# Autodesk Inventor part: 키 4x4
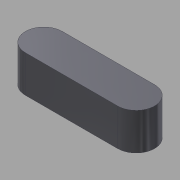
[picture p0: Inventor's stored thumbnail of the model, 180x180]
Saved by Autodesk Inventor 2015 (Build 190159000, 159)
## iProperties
Created: 2014-10
Part Number: 키 4x4
Document SubType Name: Modeling
Designer: KYOUNG IL JANG
Density: 7.86 g/cm^3
Mass: 1.65269 g
Surface Area: 2.35398 cm^2
Volume: 0.210265 cm^3
Material: 강철, 연강
Appearance: 강철 - 광택
Author: SeoGD™ [www.esajin.kr]
Revision Number: 1
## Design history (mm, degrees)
sketch "스케치1"
  geometry: L1 (-5, -2)-(5, -2); L2 (5, 2)-(-5, 2); A1 r 2 centre (5, 0) between (5, -2) and (5, 2); A2 r 2 centre (-5, 0) between (-5, 2) and (-5, -2); 2 further points
  constraints: 4 end point, 4 point on circle, 4 tangent, 2 centre point, 1 horizontal, 1 horizontal alignment, 1 midpoint, 1 parallel, 1 vertical alignment
  dimensions: "d0" = 4 distance between parallel lines of L1 L2; "d1" = 14 dimension on A1 A2
extrude "돌출1" new body sketch "스케치1" stored distance "d2" = 4; taper "d3" = 0 deg
node "솔리드1"
